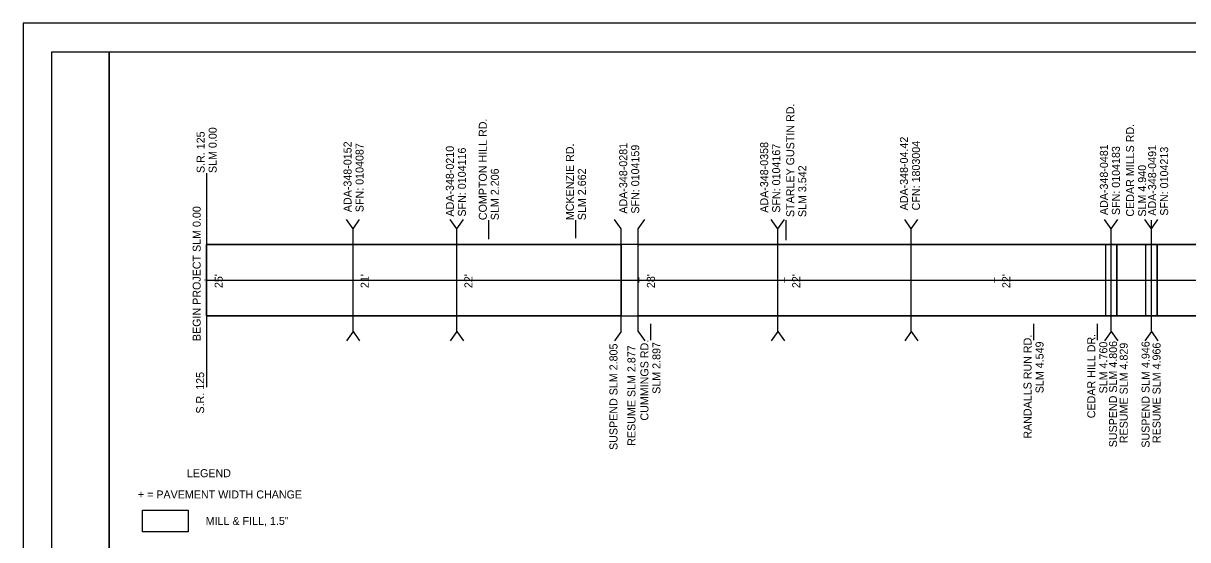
# Model space of a CAD drawing. Extents: x 0 to 34, y 0 to 22.
# Drawn here: x 0 to 20.36, y 12.96 to 22 of the extents above; entities that cross this region are included whole.
import ezdxf

# ---------------------------------------------------------------- set-up
doc = ezdxf.new("R2010")
doc.units = 0
for name, color, linetype in [('Default', 7, 'Continuous'), ('SC_Scratch1', 7, 'Continuous'), ('SH_Border', 7, 'Continuous'), ('SH_Cut_Line', 7, 'Continuous'), ('SH_Data', 7, 'Continuous'), ('SH_Text', 7, 'Continuous'), ('TX_P_1', 7, 'Continuous')]:
    doc.layers.add(name, color=color, linetype=linetype)

msp = doc.modelspace()

# ---------------------------------------------------------------- linework, layer by layer
at = {"layer": 'Default'}
for p, q in [((1.5, 21.5), (32, 21.5)), ((1.5, 21.5), (1.5, 12.819)), ((10.454, 18.403), (10.339, 18.567)), ((10.754, 18.403), (10.868, 18.567)), ((10.454, 16.603), (10.454, 18.403)), ((10.754, 16.603), (10.754, 18.403)), ((3.206, 18.128), (3.206, 16.878)), ((3.206, 17.503), (29.606, 17.503)), ((10.454, 16.603), (10.339, 16.439)), ((10.754, 16.603), (10.868, 16.439))]:
    msp.add_line(p, q, dxfattribs=at)
for points in [[(3.206, 18.128), (3.206, 16.878), (29.606, 16.878), (29.606, 18.128), (29.606, 18.128), (3.206, 18.128), (3.206, 16.878), (29.606, 16.878), (29.606, 18.128)], [(2.084, 13.476), (2.884, 13.476), (2.884, 13.097), (2.084, 13.097)], [(2.084, 13.476), (2.884, 13.476), (2.884, 13.097), (2.084, 13.097)]]:
    msp.add_lwpolyline(points, close=True, dxfattribs=at)
at = {"layer": 'SC_Scratch1'}
for points in [[(3.206, 18.128), (10.454, 18.128), (10.454, 16.878), (3.206, 16.878)], [(10.754, 18.128), (29.606, 18.128), (29.606, 16.878), (10.754, 16.878)], [(10.754, 18.128), (18.922, 18.128), (18.922, 16.878), (10.754, 16.878)], [(19.122, 18.128), (19.625, 18.128), (19.625, 16.878), (19.122, 16.878)], [(19.825, 18.128), (29.606, 18.128), (29.606, 16.878), (19.825, 16.878)]]:
    msp.add_lwpolyline(points, close=True, dxfattribs=at)
at = {"layer": 'SH_Border'}
for points in [[(0.5, 21.5), (1.5, 21.5), (1.5, 0.5), (0.5, 0.5)], [(1.5, 21.5), (33.5, 21.5), (33.5, 0.5), (1.5, 0.5)]]:
    msp.add_lwpolyline(points, close=True, dxfattribs=at)
at = {"layer": 'SH_Cut_Line'}
msp.add_lwpolyline([(0, 0), (34, 0), (34, 22), (0, 22)], close=True, dxfattribs=at)
at = {"layer": 'SH_Data'}
for p, q in [((18.922, 18.128), (18.922, 16.878)), ((19.122, 18.128), (19.122, 16.878)), ((19.625, 18.128), (19.625, 16.878)), ((19.825, 18.128), (19.825, 16.878))]:
    msp.add_line(p, q, dxfattribs=at)
for points in [[(3.206, 18.128), (10.454, 18.128), (10.454, 16.878), (3.206, 16.878)], [(10.754, 18.128), (18.922, 18.128), (18.922, 16.878), (10.754, 16.878)], [(19.122, 16.878), (19.122, 18.128), (19.625, 18.128), (19.625, 16.878)], [(19.825, 18.128), (29.606, 18.128), (29.606, 16.878), (19.825, 16.878)]]:
    msp.add_lwpolyline(points, close=True, dxfattribs=at)
at = {"layer": 'SH_Text'}
for p, q in [((3.206, 19.378), (3.206, 15.628)), ((5.766, 18.403), (5.651, 18.567)), ((5.766, 18.403), (5.881, 18.567)), ((7.58, 18.403), (7.465, 18.567)), ((7.58, 18.403), (7.695, 18.567)), ((8.14, 18.218), (8.14, 18.553)), ((9.662, 18.239), (9.662, 18.553)), ((13.194, 18.403), (13.079, 18.567)), ((13.194, 18.403), (13.308, 18.567)), ((13.342, 18.203), (13.342, 18.553)), ((15.526, 18.403), (15.412, 18.567)), ((15.526, 18.403), (15.641, 18.567)), ((19.022, 18.403), (18.907, 18.567)), ((19.022, 18.403), (19.137, 18.567)), ((19.725, 18.403), (19.61, 18.567)), ((19.725, 18.403), (19.839, 18.567)), ((19.73, 18.164), (19.73, 18.553)), ((5.766, 16.603), (5.766, 18.403)), ((7.58, 16.603), (7.58, 18.403)), ((13.194, 16.603), (13.194, 18.403)), ((15.526, 16.603), (15.526, 18.403)), ((19.022, 16.603), (19.022, 18.403)), ((19.725, 16.603), (19.725, 18.403)), ((8.14, 18.128), (8.015, 18.128)), ((8.14, 18.128), (8.265, 18.128)), ((19.73, 18.128), (19.855, 18.128)), ((3.206, 16.878), (29.606, 16.878)), ((10.966, 16.735), (10.966, 16.453)), ((17.665, 16.735), (17.665, 16.453)), ((18.78, 16.74), (18.78, 16.453)), ((5.766, 16.603), (5.651, 16.439)), ((5.766, 16.603), (5.881, 16.439)), ((7.58, 16.603), (7.465, 16.439)), ((7.58, 16.603), (7.695, 16.439)), ((13.194, 16.603), (13.079, 16.439)), ((13.194, 16.603), (13.308, 16.439)), ((15.526, 16.603), (15.412, 16.439)), ((15.526, 16.603), (15.641, 16.439)), ((19.022, 16.603), (18.907, 16.439)), ((19.022, 16.603), (19.137, 16.439)), ((19.725, 16.603), (19.61, 16.439)), ((19.725, 16.603), (19.839, 16.439))]:
    msp.add_line(p, q, dxfattribs=at)
at = {"layer": 'TX_P_1'}
msp.add_lwpolyline([(2.084, 13.476), (2.884, 13.476), (2.884, 13.097), (2.084, 13.097)], close=True, dxfattribs=at)

# ---------------------------------------------------------------- texts
at = {"layer": 'SH_Text'}
for s, p in [('STARLEY GUSTIN RD.', (13.481, 18.607)), ('SLM 0.00', (3.381, 19.378)), ('COMPTON HILL RD.', (8.105, 18.553)), ('CEDAR MILLS RD.', (19.423, 18.615)), ('S.R. 125', (3.171, 19.378)), ('ADA-348-04.42', (15.469, 18.724)), ('ADA-348-0152', (5.74, 18.693)), ('SFN: 0104087', (5.95, 18.693)), ('ADA-348-0210', (7.529, 18.616)), ('SFN: 0104116', (7.739, 18.616)), ('MCKENZIE RD.', (9.627, 18.553)), ('ADA-348-0281', (10.56, 18.667)), ('SFN: 0104159', (10.77, 18.667)), ('ADA-348-0358', (13.025, 18.683)), ('SFN: 0104167', (13.235, 18.683)), ('CFN: 1803004', (15.679, 18.724)), ('ADA-348-0481', (18.965, 18.642)), ('SFN: 0104183', (19.175, 18.642)), ('ADA-348-0491', (19.809, 18.631)), ('SFN: 0104213', (20.019, 18.631)), ('SLM 2.206', (8.315, 18.553)), ('SLM 2.662', (9.837, 18.553)), ('SLM 3.542', (13.691, 18.607)), ('SLM 4.940', (19.633, 18.615)), ('BEGIN PROJECT SLM 0.00', (3.102, 16.436)), ('+', (3.276, 17.45)), ("25'", (3.486, 17.364)), ('+', (5.83, 17.45)), ("21'", (6.04, 17.364)), ('+', (7.643, 17.45)), ("22'", (7.853, 17.364)), ('+', (10.834, 17.45)), ("28'", (11.044, 17.364)), ('+', (13.375, 17.45)), ("22'", (13.585, 17.364)), ('+', (17.048, 17.45)), ("22'", (17.258, 17.364)), ('RANDALLS RUN RD.', (17.63, 14.727)), ('CEDAR HILL DR.', (18.745, 15.085)), ('SUSPEND SLM 2.805', (10.39, 14.53)), ('RESUME SLM 2.877', (10.704, 14.603)), ('CUMMINGS RD.', (10.931, 15.044)), ('SLM 2.897', (11.141, 15.513)), ('SLM 4.549', (17.84, 15.523)), ('SLM 4.760', (18.955, 15.52)), ('SUSPEND SLM 4.806', (19.125, 14.576)), ('RESUME SLM 4.829', (19.312, 14.649)), ('SUSPEND SLM 4.946', (19.694, 14.57)), ('RESUME SLM 4.966', (19.886, 14.65)), ('S.R. 125', (3.162, 15.167))]:
    msp.add_text(s, height=0.14, rotation=90, dxfattribs=at).set_placement(p)
at = {"layer": 'TX_P_1'}
for s, p in [('LEGEND', (2.861, 14.053)), ('+ = PAVEMENT WIDTH CHANGE', (2.004, 13.681)), ('MILL & FILL, 1.5"', (3.189, 13.217))]:
    msp.add_text(s, height=0.14, dxfattribs=at).set_placement(p)

doc.saveas('drawing.dxf')
